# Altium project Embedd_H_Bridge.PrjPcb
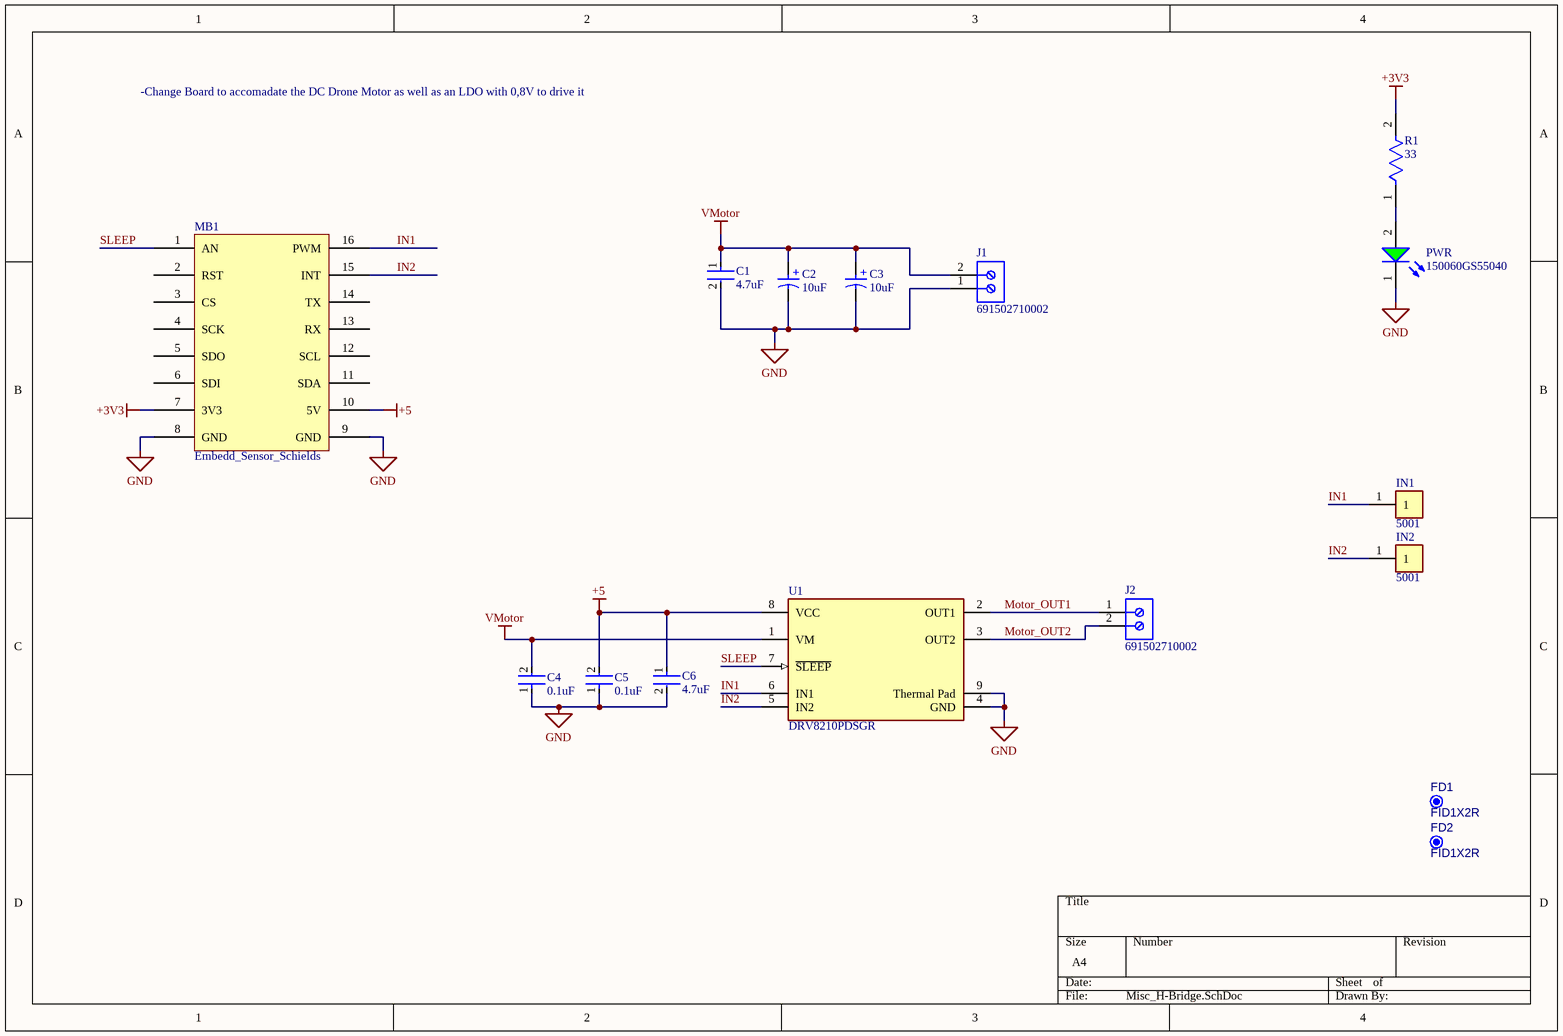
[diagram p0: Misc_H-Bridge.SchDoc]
1 sheet, 16 parts. Net scope: global (net labels, ports and power ports of the same name join across sheets).
Board file: Misc_PCB_H-Bridge.PcbDoc

## Sheet Misc_H-Bridge.SchDoc
size A4; SheetNumber: 1; SheetTotal: 1

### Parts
C1  4.7uF  [FP-CL10-IPC_C]
C2  10uF  [WCAP-ASLI_D5H5.5]
C3  10uF  [WCAP-ASLI_D5H5.5]
C4  0.1uF  [FP-CC0603-DA-IPC_A]
C5  0.1uF  [FP-CC0603-DA-IPC_A]
C6  4.7uF  [FP-CL10-IPC_C]
FD1  FID1X2R  [FID1X2R]  (no BOM)
FD2  FID1X2R  [FID1X2R]  (no BOM)
IN1  5001  [FP-5001-MFG]
IN2  5001  [FP-5001-MFG]
J1  691502710002  [691502710002]
J2  691502710002  [691502710002]
MB1  Embedd_Sensor_Schields  [Embedd_add_on_board_25,4 x 30,58]
PWR  150060GS55040  [WL-SMCD_0603]
R1  33  [FP-CRCW0603-e3-IPC_A]
U1  DRV8210PDSGR  [FP-DSG0008A-MFG]

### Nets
+3V3: MB1.7(3V3) R1.2
+5: C5.2 C6.1 MB1.10(5V) U1.8(VCC)
GND: C1.2 C2.2(N) C3.2(N) C4.1 C5.1 C6.2 J1.1 MB1.8(GND) MB1.9(GND) PWR.1(K) U1.4(GND) U1.9(Thermal_Pad)
VMotor: C1.1 C2.1(P) C3.1(P) C4.2 J1.2 U1.1(VM)
IN1: IN1.1 MB1.16(PWM) U1.6(IN1)
IN2: IN2.1 MB1.15(INT) U1.5(IN2)
Motor_OUT1: J2.1 U1.2(OUT1)
Motor_OUT2: J2.2 U1.3(OUT2)
SLEEP: MB1.1(AN) U1.7(~{SLEEP})
NetPWR_2: PWR.2(A) R1.1

Not connected (* = marked no-connect by the designer): MB1 2(RST) 3(CS) 4(SCK) 5(SDO) 6(SDI) 11(SDA) 12(SCL) 13(RX) 14(TX)

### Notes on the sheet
- -Change Board to accomadate the DC Drone Motor as well as an LDO with 0,8V to drive it

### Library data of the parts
C1 C6 = CMP-13271-003017-1: Cap Ceramic 4.7uF 10V X5R ±10% Pad SMD 0603 +85°C T/R
C2 C3 = CMP-03913-53914615-1: 865080642006 WCAP-ASLI Aluminum Electrolytic Capacitors; Tolerance: 20%; Ripple Current (AC): 95mA; Polarity: Polar; Leakage Current: 5µA; Voltage Rating: 50V; ESR (Equivalent Series Resistance): 1.63932Ω; Capacitance: 10µF; Impedance: 2.8Ω; Insulation Resistance: 10MΩ; Life (Hours): 2000hours
C4 C5 = CMP-03422-001490-1: CAP CER 0.1UF 50V X7R 0603; Capacitance: 100nF; Tolerance: 5%
FD1 FD2 = CMP-00028-00005-4: Fiducial - Round 1x2mm
IN1 IN2 = CMP-2000-05181-2: PC TEST POINT MINIATURE BLACK; Body Material: Bronze; Plating: Silver; Inside Diameter: 1.27mm; Hole Diameter: 1.6mm; Number of Ports: 1; Outside Diameter: 2.54mm; Insulation: Insulated
J1 J2 = CMP-1502-03333-2: NexarPartId: 106069304; Pitch: 5mm
MB1 = CMP-00030-00005-3: Footprint for sensor shields
PWR = CMP-03913-90235563-2: 150060GS55040 WL-SMCD SMT Mono-color Chip LED Diffused; Forward Voltage: 3.2V; Forward Current: 60mA; Luminous Intensity: 430mcd; Peak Wavelength: 520nm; Viewing Angle: 140°; Wavelength: 525nm; Max Reverse Voltage (DC): 5V
R1 = CMP-2000-03250-2: RES Thick Film, 33Ω, 1%, 0.1W, 100ppm/°C, 0603; Voltage Rating: 75V; Max Power Dissipation: 100mW; Resistance: 33R
U1 = CMP-04915-000081-1: 11V, 1A H-BRIDGE MOTOR DRIVER, P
